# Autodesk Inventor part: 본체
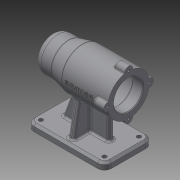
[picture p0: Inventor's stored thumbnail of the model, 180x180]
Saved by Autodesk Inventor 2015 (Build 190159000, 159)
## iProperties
Created: 2019-07
Part Number: 본체
Material: 일반
Document SubType Name: Modeling
Designer: now
Density: 1 g/cm^3
Appearance: 기본값
Author: now
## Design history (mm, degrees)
sketch "스케치1"
  geometry: L1 (56, 25)-(31, 25); L2 (31, 25)-(11, 30); L3 (11, 30)-(-56, 30); L4 (-56, 30)-(-56, 0); L5 (-56, 0)-(56, 0); L6 (56, 0)-(56, 25); 2 further points
  constraints: 12 end point, 2 parallel, 2 perpendicular, 1 coincident, 1 horizontal, 1 midpoint
  dimensions: "d0" = 25 distance of L1.start L1.end; "d1" = 45 horizontal distance of L2.end L1.start; "d2" = 112 distance of L4.end L5.end; "d3" = 30 distance of L3.end L4.end; "d4" = 25 distance of L5.end L1.start
revolve "회전1" sketch "스케치1" stored, may be unused: angle "d5" = 90 deg
node "작업 평면1"
sketch "스케치2"
  geometry: L1 (-56, 35)-(56, 35); L2 (56, 35)-(56, -35); L3 (56, -35)-(-56, -35); L4 (-56, -35)-(-56, 35); L5 (-56, 35)-(56, -35); L6 (56, 35)-(-56, -35); 1 further point
  constraints: 12 end point, 2 midpoint, 2 parallel, 1 horizontal, 1 perpendicular
  dimensions: "d7" = 112 distance of L2.end L3.end; "d8" = 70 distance of L1.end L2.end
extrude "돌출1" join sketch "스케치2" distance "d9" = 10; taper "d10" = 0 deg
sketch "스케치3"
  geometry: L1 (56, 35)-(-56, 35) reference; L2 (-56, 35)-(-56, -35) reference; L3 (-56, -35)-(56, -35) reference; L4 (56, -35)-(56, 35) reference; L5 (-36, -4)-(31, -4); L6 (31, -4)-(31, 4); L7 (31, 4)-(-36, 4); L8 (-36, 4)-(-36, -4); L9 (-4, -28)-(4, -28); L10 (4, -28)-(4, 28); L11 (4, 28)-(-4, 28); L12 (-4, 28)-(-4, -28); 1 further point
  constraints: 16 end point, 4 parallel, 2 horizontal, 2 perpendicular
  dimensions: "d11" = 8 distance of L10.end L11.end; "d12" = 8 distance of L7.end L5.start; "d13" = 4 distance from line of L5 point (0, 0); "d14" = 4 distance from line of point (0, 0) L10; "d15" = 20 distance between parallel lines of L2 L8; "d16" = 25 distance between parallel lines of L4 L6; "d17" = 7 distance between parallel lines of L3 L9; "d18" = 7 distance between parallel lines of L1 L11
extrude "돌출2" new body sketch "스케치3" stored distance "d19" = 10; taper "d20" = 0 deg
feature "면 기울기1" dims angle "d21" = 10 deg
feature "면 기울기2" dims angle "d22" = 20 deg
feature "결합1"
  node "솔리드1"
sketch "스케치4"
  geometry: C1 r 30 at (0, 0) reference
hole "구멍1" sketch "스케치4" at (0, 0) diameter "d23" = 42; stored, may be unused: countersink angle "d27" = 90 deg, drill point angle "d29" = 0 deg; dims "d24" = 6, "d25" = 4, "d26" = 2, "d28" = 15
sketch "스케치5"
  geometry: C1 r 21 at (0, 0) reference
hole "구멍2" sketch "스케치5" at (0, 0) diameter "d30" = 48; stored, may be unused: countersink angle "d34" = 90 deg, drill point angle "d36" = 0 deg; dims "d31" = 6, "d32" = 4, "d33" = 2, "d35" = 54
sketch "스케치6"
  geometry: C1 r 24 at (0, 0) reference
hole "구멍3" sketch "스케치6" at (0, 0) diameter "d37" = 42; stored, may be unused: countersink angle "d41" = 90 deg, drill point angle "d43" = 0 deg; dims "d38" = 6, "d39" = 4, "d40" = 2, "d42" = 12
sketch "스케치7"
  geometry: C1 r 21 at (0, 0) reference
hole "구멍4" sketch "스케치7" at (0, 0) diameter "d44" = 35; stored, may be unused: countersink angle "d48" = 90 deg, drill point angle "d50" = 0 deg; dims "d45" = 6, "d46" = 4, "d47" = 2, "d49" = 18
sketch "스케치8"
  geometry: C1 r 17.5 at (0, 0) reference
hole "구멍5" sketch "스케치8" at (0, 0) diameter "d51" = 32; stored, may be unused: countersink angle "d55" = 90 deg, drill point angle "d57" = 0 deg; dims "d52" = 6, "d53" = 4, "d54" = 2, "d56" = 4
sketch "스케치9"
  geometry: C1 r 16 at (0, 0) reference
hole "구멍6" sketch "스케치9" at (0, 0) diameter "d58" = 21; stored, may be unused: countersink angle "d62" = 90 deg, drill point angle "d64" = 0 deg; dims "d59" = 6, "d60" = 4, "d61" = 2, "d63" = 3
fillet "모깎기1" dims "d65" = 3
fillet "모깎기2" dims "d66" = 3
fillet "모깎기3" dims "d67" = 0.3
sketch "스케치10"
  geometry: C1 r 6 at (-30, 0); 1 further point
  constraints: 1 centre point, 1 horizontal alignment, 1 other
  dimensions: "d68" = 12 diameter of C1
extrude "돌출3" join sketch "스케치10" distance "d69" = 16; taper "d70" = 0 deg
fillet "모깎기4" dims "d71" = 3
fillet "모깎기5" dims "d72" = 1
sketch "스케치11"
  geometry: A1 r 6 centre (60, 0) between (60.171, -5.998) and (60.171, 5.998) reference; A2 r 6 centre (30, 30) between (35.998, 30.171) and (24.002, 30.171) reference; A3 r 6 centre (0, 0) between (-0.171, 5.998) and (-0.171, -5.998) reference; A4 r 6 centre (30, -30) between (24.002, -30.171) and (35.998, -30.171) reference
hole "구멍7" sketch "스케치11" at (0, 0), (30, -30), (60, 0), (30, 30) diameter "d76" = 3.242; stored, may be unused: countersink angle "d80" = 90 deg, drill point angle "d82" = 118 deg; dims "d77" = 8, "d78" = 4, "d79" = 2, "d81" = 11
sketch "스케치12"
  geometry: C1 r 3 at (10, -60); C2 r 3 at (10, -10); 1 further point
  constraints: 2 centre point
  dimensions: "d83" = 50 distance of C2.centre C1.centre; "d85" = 6 diameter of C1; "d86" = 6 diameter of C2; "d87" = 25 vertical distance of point (56, -35) C1.centre; "d88" = 46 horizontal distance of point (56, -35) C1.centre; "d89" = 46 horizontal distance of C2.centre point (56, -35)
extrude "돌출4" cut sketch "스케치12" stored distance "d90" = 16; taper "d91" = 0 deg
fillet "모깎기6" dims "d92" = 10
chamfer "모따기1" distance "d93" = 3; stored, may be unused: second distance "d94" = 2, angle "d95" = 45 deg
fillet "모깎기7" dims "d96" = 10
fillet "모깎기8" dims "d97" = 3
fillet "모깎기9" dims "d98" = 3
fillet "모깎기10" dims "d99" = 3
fillet "모깎기11" dims "d100" = 3
chamfer "모따기2" distance "d101" = 1; stored, may be unused: second distance "d102" = 2, angle "d103" = 45 deg
node "작업 평면2"
sketch "스케치13"
  geometry: L1 (56, 36)-(56, 30.171) reference; 2 further points
  constraints: 1 horizontal alignment, 1 other
  dimensions: "d105" = 42 distance from line of point (14, 0) L1
feature "엠보싱1" sketch "스케치13" dims "d0" = 25, "d1" = 45, "d2" = 112, "d3" = 30, "d4" = 25, "d106" = 0.5, "d107" = 0
pattern_circular "원형 패턴1" dims "d74" = 360 deg
mirror "대칭1"
node "솔리드2"
other parameters: "d104" = -30.5
